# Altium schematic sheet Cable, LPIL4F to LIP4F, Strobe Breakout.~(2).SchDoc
size B; Organization: Monterey Bay Aquarium Research Institute; Address1: 7700 Sandholdt Rd; Address2: Moss Landing, CA 95039-9644; CompanyName: MBARI
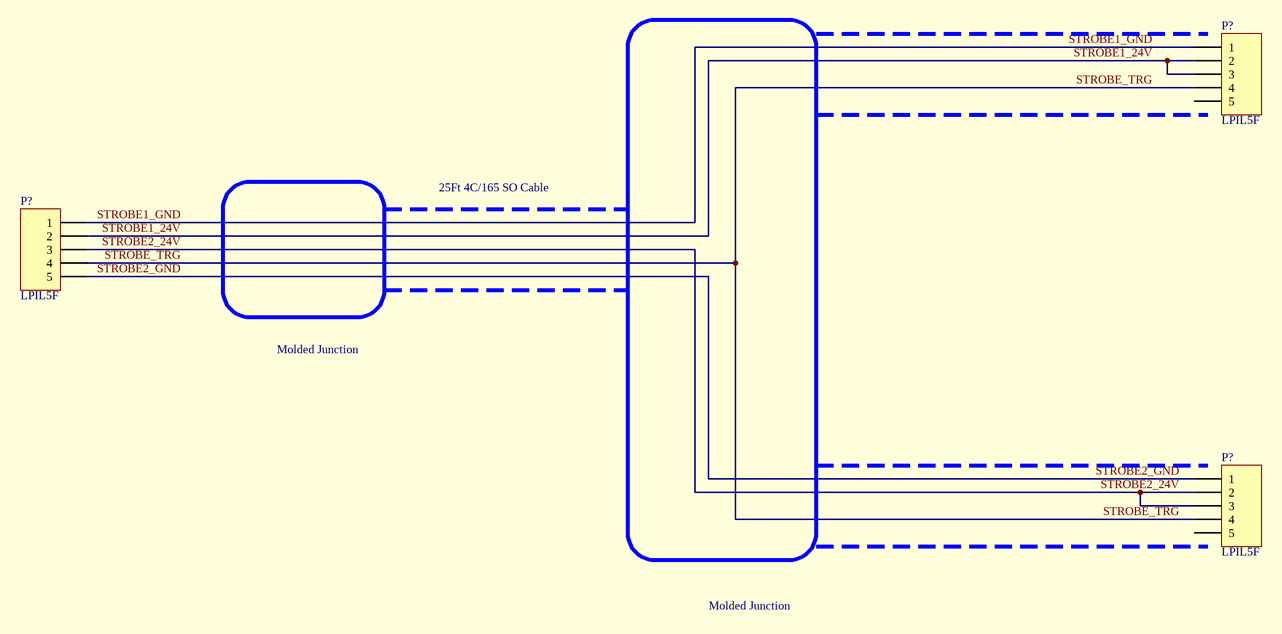
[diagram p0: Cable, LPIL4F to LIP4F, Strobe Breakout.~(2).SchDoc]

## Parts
(Parts that share a designator on the sheet are numbered #1, #2 ... from top to bottom, then left to right.)
P?#1  LPIL5F  [HDR1X5]
P?#2  LPIL5F  [HDR1X5]
P?#3  LPIL5F  [HDR1X5]

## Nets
STROBE1_24V: P?#1.2 P?#1.3 P?#2.2
STROBE1_GND: P?#1.1 P?#2.1
STROBE2_24V: P?#2.3 P?#3.2 P?#3.3
STROBE2_GND: P?#2.5 P?#3.1
STROBE_TRG: P?#1.4 P?#2.4 P?#3.4

Not connected (* = marked no-connect by the designer): P?#1 5; P?#3 5

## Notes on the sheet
- 25Ft 4C/165 SO Cable
- Molded Junction

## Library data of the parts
P?#1-P?#3 = Header 5: Header, 5-Pin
